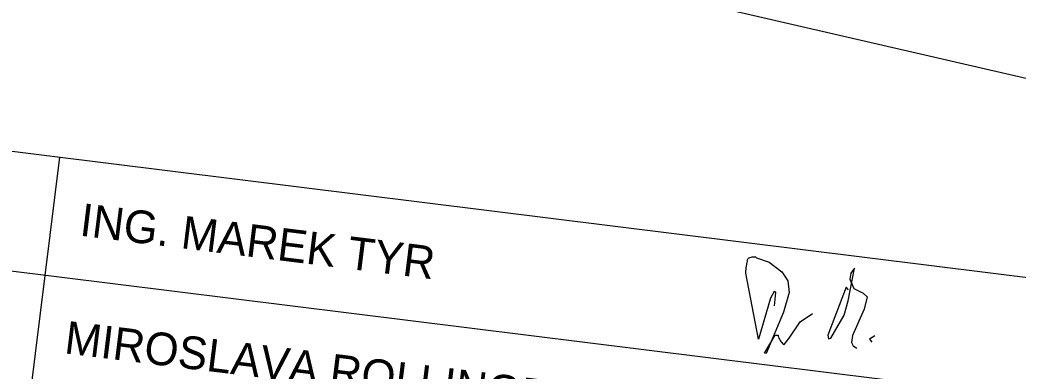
# Model space of a CAD drawing. Extents: x -804850 to -804680, y -1165160 to -1165081.
# Drawn here: x -804716.25 to -804704.15, y -1165142.24 to -1165137.98 of the extents above; entities that cross this region are included whole.
import ezdxf

# ---------------------------------------------------------------- set-up
doc = ezdxf.new("R2010")
doc.units = 0
for name, color, linetype in [('1_2000 - úřady', 7, 'Continuous'), ('Rozpiska TMS', 7, 'Continuous'), ('Stsitu', 7, 'Continuous')]:
    doc.layers.add(name, color=color, linetype=linetype)

msp = doc.modelspace()

# ---------------------------------------------------------------- linework, layer by layer
at = {"layer": '1_2000 - úřady'}
for p, q in [((-804715.774, -1165139.645), (-804716.663, -1165146.79)), ((-804723.782, -1165140.1), (-804702.935, -1165142.693))]:
    msp.add_line(p, q, dxfattribs=at)
msp.add_lwpolyline([(-804723.604, -1165138.671), (-804691.451, -1165142.67), (-804692.162, -1165148.386), (-804724.315, -1165144.387)], close=True, dxfattribs=at)
at = {"layer": 'Rozpiska TMS'}
for p, q in [((-804707.322, -1165140.865), (-804707.171, -1165140.921)), ((-804707.171, -1165140.921), (-804707.016, -1165141.036)), ((-804706.211, -1165141.39), (-804706.133, -1165140.992)), ((-804706.133, -1165140.992), (-804706.181, -1165141.054)), ((-804707.299, -1165141.852), (-804707.454, -1165141.053)), ((-804707.016, -1165141.036), (-804706.945, -1165141.147)), ((-804706.181, -1165141.054), (-804706.191, -1165141.127)), ((-804706.191, -1165141.127), (-804706.144, -1165141.239)), ((-804706.945, -1165141.147), (-804706.926, -1165141.289)), ((-804706.235, -1165141.224), (-804706.46, -1165141.806)), ((-804706.206, -1165141.255), (-804706.235, -1165141.224)), ((-804706.144, -1165141.239), (-804706.03, -1165141.297)), ((-804707.153, -1165141.356), (-804707.299, -1165141.852)), ((-804707.11, -1165141.276), (-804707.153, -1165141.356)), ((-804707.087, -1165141.289), (-804707.11, -1165141.276)), ((-804707.103, -1165141.45), (-804707.087, -1165141.289)), ((-804706.926, -1165141.289), (-804706.996, -1165141.525)), ((-804706.03, -1165141.297), (-804705.982, -1165141.341)), ((-804705.982, -1165141.341), (-804706.017, -1165141.49)), ((-804706.26, -1165141.561), (-804706.211, -1165141.39)), ((-804706.017, -1165141.49), (-804706.161, -1165141.809)), ((-804706.996, -1165141.525), (-804707.207, -1165142.027)), ((-804706.792, -1165141.642), (-804706.646, -1165141.544)), ((-804706.42, -1165141.841), (-804706.26, -1165141.561)), ((-804706.929, -1165141.84), (-804706.792, -1165141.642)), ((-804707.227, -1165142.024), (-804707.095, -1165141.806)), ((-804707.095, -1165141.806), (-804707.059, -1165141.807)), ((-804706.987, -1165141.918), (-804706.929, -1165141.84)), ((-804706.46, -1165141.806), (-804706.45, -1165141.851)), ((-804706.45, -1165141.851), (-804706.42, -1165141.841)), ((-804706.161, -1165141.809), (-804706.172, -1165141.893)), ((-804705.887, -1165141.812), (-804705.953, -1165141.852)), ((-804705.953, -1165141.852), (-804705.926, -1165141.892)), ((-804706.172, -1165141.893), (-804706.149, -1165141.936)), ((-804706.149, -1165141.936), (-804706.108, -1165141.962)), ((-804707.207, -1165142.027), (-804707.227, -1165142.024))]:
    msp.add_line(p, q, dxfattribs=at)
for centre, major_axis, ratio, start_param, end_param in [((-804707.442, -1165140.968), (0.0126, 0.0853), 0.076546, 0.000522, 3.142115), ((-804707.376, -1165140.874), (0.0537, 0.0082), 0.272761, 0.031583, 3.173176), ((-804707.023, -1165141.862), (0.0361, -0.0552), 0.229475, 3.102154, 6.243747)]:
    msp.add_ellipse(centre, major_axis=major_axis, ratio=ratio, start_param=start_param, end_param=end_param, dxfattribs=at)
at = {"layer": 'Stsitu'}
msp.add_line((-804724.988, -1165133.826), (-804700.388, -1165139.537), dxfattribs=at)

# ---------------------------------------------------------------- texts
at = {"layer": '1_2000 - úřady'}
for s, p in [('ING. MAREK TYR', (-804715.541, -1165140.596)), ('MIROSLAVA ROLLINGEROVÁ', (-804715.727, -1165142.024))]:
    msp.add_text(s, height=0.396, rotation=352.9443, dxfattribs=at).set_placement(p)

doc.saveas('drawing.dxf')
